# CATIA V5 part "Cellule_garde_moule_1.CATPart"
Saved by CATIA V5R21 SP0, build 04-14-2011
Part number: Moule_cellule_garde
Bounding box of the stored display mesh (mm): x -30 to 30, y -120 to 120, z -20 to 0
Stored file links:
  C:\Users\zerma\Pictures\CAO\Cellule_garde_moule_1.CATPart
  Product1.CATProduct
  C:\Users\zerma\Pictures\CAO\Moule_v1.CATPart
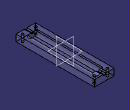
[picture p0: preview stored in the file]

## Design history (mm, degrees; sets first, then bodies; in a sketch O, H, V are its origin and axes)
Body1 (main body)
  Sketch1 on yz-plane, origin (0, 0, 0), H (0, 1, 0), V (0, 0, 1)
    line L1 (-95, -12.5) -> (95, -12.5)
    point P1 (-95, -12.5)
    line L2 (-100, -15) -> (100, -15)
    point P3 (-100, -15)
    line L3 (-95, -12.5) -> (-95, 0)
    point P5 (-95, 0)
    line L4 (-100, -15) -> (-100, 0)
    point P6 (-100, 0)
    line L5 (-95, 0) -> (-100, 0)
    point P7 (100, 0)
    point P8 (100, -15)
    line L6 (100, -15) -> (100, 0)
    point P9 (95, 0)
    line L7 (95, 0) -> (100, 0)
    point P10 (95, -12.5)
    line L8 (95, -12.5) -> (95, 0)
    distance L1 H = 12.5
    distance L1 L2 = 2.5
    length L4 = 15
    distance L4 L3 = 5
    length L1 = 190
    length L2 = 200
    distance V L3 = 95
    horizontal: L1 H, L2 H, L5 H
    vertical: L3 V, L4 V
    symmetry: P6 P7 V, P3 P8 V, L4 L6 V, P5 P9 V, L5 L7 V, P1 P10 V, L3 L8 V
  Shaft1: profile Sketch1, axis Sketch1.H, angle 360
  Sketch2 on face of Shaft1 from Sketch1.L4, origin (0, -100, 0), H (1, 0, 0), V (0, 0, 1)
    line L1 (-10, 2.5) -> (10, 2.5)
    line L2 (10, 2.5) -> (10, -2.5)
    line L3 (10, -2.5) -> (-10, -2.5)
    line L4 (-10, -2.5) -> (-10, 2.5)
    length L2 = 5
    length L1 = 20
    horizontal: L1 H, L3 H
    vertical: L2 V, L4 V
    symmetry: L3 L1 H, L4 L2 V
  Pad1: profile Sketch2, direction (0, -1, 0), length 15
  Sketch3 on face of Pad1 from Sketch2.L1, origin (0, 0, 2.5), H (1, 0, 0), V (0, 1, 0)
    circle A1 centre (0, -107.5) radius 2.5
    point P1 (0, -107.5)
    reference intersected line E1 (14.7902, -100) -> (-14.7902, -100) from face of Shaft1 from Sketch1.L4
    radius A1 = 2.5
    distance P1 E1 = 7.5
    coincidence: P1 V
  Pocket1: profile Sketch3, direction (0, 0, -1), length 5, mirrored extent
  Fillet1: radius 2, on edge [face of Pad1 from Sketch2.L4 | end face of Pad1]; edge [face of Pad1 from Sketch2.L1 | end face of Pad1]; edge [face of Pad1 from Sketch2.L3 | end face of Pad1]; edge [face of Pad1 from Sketch2.L2 | end face of Pad1]; edge [face of Pad1 from Sketch2.L2 | face of Pad1 from Sketch2.L3]; edge [face of Shaft1 from Sketch1.L4 | face of Pad1 from Sketch2.L3]; edge [face of Pad1 from Sketch2.L3 | face of Pad1 from Sketch2.L4]; edge [face of Pocket1 from Sketch3.A1 | face of Pad1 from Sketch2.L3]; edge [face of Pad1 from Sketch2.L4 | face of Pad1 from Sketch2.L1]; edge [face of Pad1 from Sketch2.L1 | face of Pad1 from Sketch2.L2]; edge [face of Shaft1 from Sketch1.L4 | face of Pad1 from Sketch2.L1]; edge [face of Shaft1 from Sketch1.L4 | face of Pad1 from Sketch2.L4]; edge [face of Shaft1 from Sketch1.L4 | face of Pad1 from Sketch2.L2]; face of Pad1 from Sketch2.L1
  Mirror1: of Pad1, Pocket1, Fillet1, about zx-plane
  Fillet2: radius 4, on edge [face of Shaft1 from Sketch1.L2 | face of Shaft1 from Sketch1.L6]; edge [face of Shaft1 from Sketch1.L4 | face of Shaft1 from Sketch1.L2]
Body2
  Sketch4 on xy-plane, origin (0, 0, 0), H (1, 0, 0), V (0, 1, 0)
    line L1 (30, 120) -> (30, -120)
    line L2 (30, -120) -> (-30, -120)
    line L3 (-30, -120) -> (-30, 120)
    line L4 (-30, 120) -> (30, 120)
    vertical: L1 V, L3 V
    horizontal: L2 H, L4 H
    equidistance: L1 L3 O, L2 L4 O
  Pad2: profile Sketch4, direction (0, 0, -1), length 20
  Body3
    Sketch5 on yz-plane, origin (0, 0, 0), H (0, 1, 0), V (0, 0, 1)
      line L1 (-95, -12.5) -> (95, -12.5)
      point P1 (-95, -12.5)
      line L2 (-100, -15) -> (100, -15)
      point P3 (-100, -15)
      line L3 (-95, -12.5) -> (-95, 0)
      point P5 (-95, 0)
      line L4 (-100, -15) -> (-100, -4)
      point P6 (-100, -4)
      point P7 (100, -4)
      point P8 (100, -15)
      line L5 (100, -15) -> (100, -4)
      point P9 (95, 0)
      point P10 (95, -12.5)
      line L6 (95, -12.5) -> (95, 0)
      line L7 (-100, -4) -> (-120, -4)
      line L8 (-120, -4) -> (-120, 0)
      line L9 (-120, 0) -> (-95, 0)
      point P13 (-95, 0)
      line L10 (100, -4) -> (120, -4)
      line L11 (120, -4) -> (120, 0)
      line L12 (120, 0) -> (95, 0)
      distance L1 H = 12.5
      distance L1 L2 = 2.5
      length L4 = 11
      distance L4 L3 = 5
      length L1 = 190
      length L2 = 200
      distance V L3 = 95
      length L9 = 25
      length L12 = 25
      length L11 = 4
      horizontal: L1 H, L2 H, L7 H, L9 H, L10 H, L12 H
      vertical: L3 V, L4 V, L8 V, L11 V
      symmetry: P6 P7 V, P3 P8 V, L4 L5 V, P5 P9 V, P1 P10 V, L3 L6 V
      coincidence: P13 P5
    Shaft2: profile Sketch5, axis Sketch5.H, angle 360
  Remove1: tool Body3
  Sketch6 on face of Shaft2 from Sketch5.L6, origin (0, 95, 0), H (-1, 0, 0), V (0, 0, 1)
    circle A1 centre (0, 0) radius 12.5
    reference projected circle E1 centre (0, 0) radius 12.5 from edge [face of Shaft2 from Sketch5.L1 | face of Shaft2 from Sketch5.L6]
    reference projected circle E2 centre (0, 0) radius 12.5 from edge [face of Shaft2 from Sketch5.L1 | face of Shaft2 from Sketch5.L6]
    coincidence: A1 E1
    concentricity: A1 E2
  Pocket2: profile Sketch6, direction (0, -1, 0), up to face of Shaft2 from Sketch5.L3
  Sketch7 on end face of Pad2, origin (0, 0, -20), H (1, 0, 0), V (0, -1, 0)
    circle A1 centre (20, 110) radius 3.5
    point P1 (20, 110)
    circle A2 centre (20, -110) radius 3.5
    circle A3 centre (-20, 110) radius 3.5
    circle A4 centre (-20, -110) radius 3.5
    reference projected line E1 (30, 120) -> (30, -120) from edge [end face of Pad2 | face of Pad2 from Sketch4.L1]
    reference projected line E2 (-30, 120) -> (30, 120) from edge [end face of Pad2 | face of Pad2 from Sketch4.L2]
    radius A1 = 3.5
    distance P1 E1 = 10
    distance P1 E2 = 10
    symmetry: A1 A2 H, A1 A3 V, A3 A4 H
  Pocket3: profile Sketch7, direction (0, 0, 1), length 50, mirrored extent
